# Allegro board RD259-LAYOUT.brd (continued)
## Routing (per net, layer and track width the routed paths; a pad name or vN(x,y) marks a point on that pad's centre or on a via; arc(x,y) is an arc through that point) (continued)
NETQ1_1: length 4.1
  TOP w0.3: RN14.1 64.12,11.82 Q1.1 ; RN14.1 64.06,14.08 RN13.2 ; RN14.1 64.14,14
NETR36_2: length 23.6
  BOTTOM w0.4: R36.2 19.93,34.37 20.81,34.37 21.08,34.09 ; R36.2 21.08,34.09 ; R36.2 19.92,33.84 21.34,33.84 ; 21.08,34.09 21.34,33.84 ; 21.34,33.84 21.94,33.84 26.89,28.88 26.89,22.69 27.97,21.61 ; 27.97,21.61 28.18,21.41 R37.1 27.97,20.41 27.97,21.61
NETR61_2: length 16.9
  TOP w1: 26.06,2.56 25.1,2.56 24.69,2.15 24.69,1.03 24.86,0.86 29.54,0.86 29.65,0.97 29.65,2.28 29.38,2.55 25.68,2.55 25.51,2.38 25.51,2.01 25.76,1.75 28.6,1.75
RES: length 104
  TOP w0.3: 73.19,27.21 73.19,27.63 73.07,27.75 ; 73.19,27.21 73.07,27.33 ; 73.19,27.21 74.01,26.39 74.79,26.39 ; 73.07,27.75 73.07,27.33 ; 73.07,27.75 72.87,27.95 ; 73.07,27.33 73.07,26.9 ; 73.83,26.15 74.03,25.94 74.83,25.94 ; 73.83,26.15 73.07,26.9 ; 73.83,26.15 v1(75.13,26.15) ; 68.14,25.63 68.14,25.1 68.15,25.1 ; 68.14,25.63 68.14,25.67 ; 68.14,25.63 68.38,25.4 68.38,25.15 R65.1 67.94,24.95 67.94,25.47 68.14,25.67 ; 72.87,27.95 72.87,27.11 73.07,26.9 ; 72.87,27.95 R38.2 ; 72.87,27.95 72.87,27.97 72.86,27.98 ; 70.81,29.92 70.99,29.75 C38.2 72.68,29.92 70.81,29.92 ; 70.81,29.92 70.19,30.55 IC4.4 69.23,30.54 68.42,30.54 68.14,30.26 68.14,25.67 ; R66.1 63.92,6.59
  TOP w1: 63.92,6.59 v1(65.26,6.59) ; C38.2 72.86,27.98
  BOTTOM w0.3: 65.64,6.96 65.64,6.37 65.45,6.18 65.12,6.18 64.97,6.33 64.97,6.34 64.97,6.83 ; 65.64,6.96 65.28,6.59 v1(65.26,6.59) ; 65.64,6.96 68.17,9.49 68.17,10.93 ; 32.15,19.98 30.2,19.98 R37.2 ; 32.15,19.98 31.94,20.2 ; 32.15,19.98 34.14,18 49.05,18 55.75,11.3 67.77,11.3 ; 31.78,20.35 31.63,20.51 30.29,20.51 30.13,20.35 ; 31.78,20.35 31.94,20.2 ; 31.78,20.35 30.13,20.35 ; 31.94,20.2 R37.2 ; 64.97,6.83 64.97,6.84 65.16,7.03 65.71,7.03 ; 64.97,6.83 64.94,6.8 ; 68.17,10.93 68.13,10.93 67.77,11.3 ; 68.17,10.93 68.17,11.3 ; 68.17,10.93 68.23,10.93 68.59,11.3 ; 30.13,20.35 R37.2 ; 75.39,26.12 75.39,25.73 75.1,25.44 ; 67.77,11.3 68.17,11.3 ; 75.1,25.44 75.1,15.5 70.9,11.3 68.59,11.3 ; 75.1,25.44 75.1,26.15 ; 68.17,11.3 68.59,11.3
SCK: length 2.1
  TOP w1: SCK.1 63.89,2.72 63.89,4.76 R66.2
SD: length 12.6
  TOP w0.4: 23.26,28.8 v1(23.06,29.01) ; 23.26,28.8 22.75,28.8 22.75,29.19 22.77,29.2 23.14,29.2 23.54,28.8 ; 23.26,28.8 23.54,28.8 ; 23.51,28.69 24.89,28.69 IC2.7 23.64,28.71 23.54,28.8
  BOTTOM w0.4: 23.66,29.07 24.2,29.07 24.45,28.82 ; 23.66,29.07 23.11,29.07 v1(23.06,29.01) ; 23.66,29.07 23.3,29.43 22.95,29.43 22.71,29.2 22.71,28.85 22.78,28.78 23.36,28.78 ; 23.36,28.78 23.14,29.01 v1(23.06,29.01) ; 23.36,28.78 23.59,28.56 24.8,28.56 R63.1 24.71,28.56 24.45,28.82 ; 23.36,28.78 24.42,28.78 24.45,28.82 ; 22.97,29.01 v1(23.06,29.01)
SDI: length 2.7
  TOP w1: 67.52,5.89 67.52,5.85 66.64,4.98 SDI.1
SDO: length 2
  TOP w1: R68.2 61.57,4.71 61.57,2.75 SDO.1
TX: length 36.1
  TOP w0.5: 21.17,59.22 v3(21.11,59.17)
  TOP w1: 21.11,61.74 CTX.2 ; CTX.2 21.17,65.51 ; CTX.2 21.17,59.36 ; 22.13,61.05 22.37,61.29 22.37,62.29 21.92,62.73 21.92,66 21.63,66.3 ; 22.13,61.05 22.08,61 22.08,60.27 21.19,59.38 ; 22.13,61.05 22.13,58.84 21.6,58.32 20.51,58.32 19.91,58.91 19.91,60.23 ; 21.19,59.29 21.19,59.38 ; 21.19,59.38 21.17,59.36 ; 21.17,59.36 21.11,59.3 v3(21.11,59.17) 20.98,59.17 20.45,59.7 ; 21.17,59.36 21.17,59.22 ; 20.45,59.7 19.91,60.23 ; 20.45,59.7 20.45,64.79 21.17,65.51 ; 19.91,60.23 19.91,65.4 20.14,65.62 ; 21.17,65.51 19.78,66.89 ; X.1 19.96,67.11
  vias: v5(20.08,67.05) v5(20.08,67.05)
U: length 78
  TOP w0.4: v1(12.62,38.91) 12.57,38.85 12.35,38.85 12.01,38.51 8.88,38.51
  TOP w0.5: 8.88,38.51 9.13,38.26 IC2.21 12.33,38.26 12.33,38.56 12.62,38.85 ; 9.35,38.91 v1(12.62,38.91) 12.62,38.85 12.62,38.85 ; 9.35,38.91 8.48,38.91 ; 9.35,38.91 8.17,40.08 8.15,40.08 ; 12.62,38.9 12.62,38.85 ; 12.62,38.85 12.62,38.29 12.58,38.25
  TOP w1: 9.51,44.06 9.05,43.6 ; 9.51,44.06 9.51,46.04 ; 9.51,44.06 9.53,44.06 10.23,44.76 ; 9.05,43.6 9.05,46.5 ; 9.05,43.6 8.74,43.29 ; 9.67,51.88 11.17,51.88 ; 10.23,44.76 10.93,45.46 ; 10.23,44.76 10.23,49.88 10.2,49.91 ; 10.93,45.46 10.93,50.05 11.1,50.22 ; 10.93,45.46 10.93,45 8.15,42.21 ; 8.15,39.24 7.83,39.55 7.83,42.38 8.15,42.69 ; 8.15,39.24 8.15,42.21 ; 8.15,39.24 8.88,38.51 ; 9.51,46.04 9.51,47.34 ; 9.51,46.04 9.05,46.5 ; 9.51,47.34 9.51,48.27 ; 9.51,47.34 7.55,49.31 7.55,49.86 7.93,49.86 9.51,48.27 ; 8.15,42.21 8.15,42.69 ; 8.15,42.69 8.74,43.29 ; 9.77,50.17 9.51,49.92 9.51,48.27 ; 9.05,46.5 8.74,46.81 ; 8.74,46.81 6.77,48.78 v1(6.77,49.14) ; 8.74,46.81 8.74,43.29
  BOTTOM w1: 7.85,51.22 7.85,52.06 7.2,52.71 5.87,52.71 5.44,52.28 5.44,49.43 v1(5.73,49.14) v1(6.77,49.14) 8.46,50.83 8.46,51.33 ; v1(12.62,38.91) 13.81,38.91 C15.1 13.94,39.04 13.86,39.13
  vias: v5(5.89,51.19) v5(5.89,51.19)
V: length 83
  TOP w0.4: 9.61,30.21 9.27,30.55 7.43,30.55 6.99,31 6.27,31 ; 9.61,30.21 9.95,29.88 ; 9.61,30.21 6.34,30.21 6.52,29.68 ; 11.19,29.88 IC2.26 11.23,29.86 11.28,29.81 11.28,29.8 11.4,29.68 11.51,29.57 12.18,29.57 12.35,29.41 ; 10.07,29.76 9.17,28.86 8.54,28.86 ; 9.95,29.88 9.11,29.88 ; 9.95,29.88 10.19,29.88 ; 2.63,30.11 2.17,30.56
  TOP w0.5: 11.19,29.88 10.19,29.88
  TOP w1: 4.17,28.01 2.22,28.01 1.17,29.06 ; 4.17,28.01 4.28,28.12 ; 4.17,28.01 8.01,28.01 8.86,28.86 ; 1.13,31.82 1.17,31.82 ; 1.13,31.82 1.13,29.1 1.17,29.06 ; 1.13,31.82 1.13,32.06 1.58,32.51 2.94,32.51 ; 1.17,31.82 1.17,29.06 ; 1.17,31.82 1.5,32.15 2.32,32.15 4.37,30.11 ; 4.37,30.11 4.37,31.07 2.94,32.51 ; 4.37,30.11 5.98,30.11 ; 4.37,30.11 3.12,28.86 ; 4.37,30.11 2.63,30.11 ; 5.98,30.11 6.52,29.68 ; 5.98,30.11 6.11,30.11 ; 5.98,30.11 3.58,32.51 2.94,32.51 ; 6.52,29.68 6.41,29.68 ; 6.52,29.68 5.72,29.6 4.22,29.6 v1(3.75,29.14) ; 6.52,29.68 9.11,29.68 ; 3.12,28.86 8.54,28.86 9.24,29.55 9.11,29.68 ; 3.12,28.86 1.37,28.86 ; 12.32,29.68 9.11,29.68
  BOTTOM w0.4: 13.68,29.27 13.25,29.7
  BOTTOM w1: 13.55,29.52 13.33,29.52 13.15,29.7 ; 13.55,29.52 13.37,29.7 13.15,29.7 ; 13.55,29.52 13.68,29.39 C14.1 ; 13.15,29.7 v1(12.38,29.7)
  BOTTOM w1.2: 3.18,28.56 3.18,31.96 ; 3.18,28.56 2.78,28.16 ; 3.18,28.56 3.18,28.16 2.78,28.16 ; 3.18,28.56 v1(3.75,29.14) 3.75,30.66 3.82,30.72 3.82,31.33 3.18,31.96 ; 3.18,31.96 2.61,32.53 1.77,32.53 1.77,32.52 1.05,31.79 1.05,31.42 1.05,31.42 1.05,29.36 1.13,29.27 1.13,29.26 2.22,28.17 ; 2.78,28.16 2.69,28.16
  vias: v6(2.17,30.56)
VM: length 38.5
  TOP w1: 33.89,2.64 33,1.75 32.03,1.75 ; 33.89,2.64 v4(34.63,3.38) 34.03,3.38 33.89,3.24 ; 33.89,2.64 33.89,3.24 ; 33.89,3.24 33.89,5.02 34.32,5.45 35.4,5.45 35.94,4.91 35.94,1.11 35.69,0.86 31.38,0.86 31.38,2.52 33.18,2.52 33.89,3.24 ; 33.89,3.24 33.6,2.94
  BOTTOM w1: 33.72,4.28 33.72,4.93 34.34,5.54 35.49,5.54 35.87,5.16 v1(35.87,1.02) 35.87,1.02 35.72,0.86 32.61,0.86 32.5,0.98 32.5,2.35 32.77,2.63 33.28,2.63 33.72,3.07 33.72,4.28 ; 33.72,4.28 v4(34.63,3.38)
  vias: v1(33.91,1.11) v1(34.93,1.06)
VM+310V: length 186.7
  TOP w0.4: v2(8.53,34.84) 8.77,34.84 9.06,34.55 ; 8.54,34.8 8.54,34.81 ; v2(8.54,33.63) 8.61,33.56
  TOP w0.5: 9.06,34.55 11.24,34.55 ; 8.61,33.56 11.17,33.56
  TOP w1: 8.98,34.9 8.92,34.96 7.94,34.96 7.79,34.81 7.79,34.08 ; 8.98,34.9 9.09,34.79 ; 8.98,34.9 7.87,34.9 ; 9.09,34.79 8.58,34.79 8.54,34.83 ; 9.09,34.79 9.33,34.55 ; 9.79,34.09 11.75,34.09 ; 9.79,34.09 9.33,34.55 ; 9.79,34.09 9.26,33.56 9.2,33.49 8.37,33.49 7.79,34.08 ; 22.48,0.86 22.5,0.88 22.6,0.88 22.6,3.9 ; 9.33,34.55 8.87,34.08 8.54,34.08 ; 8.54,34.08 8.54,33.63 v2(8.54,33.63) ; 8.54,34.08 7.79,34.08 ; 8.54,34.08 8.54,34.83 ; 8.54,34.83 v2(8.53,34.84)
  TOP w1.2: 22.22,0.96 21.8,1.37
  TOP w2: 19.16,2.96 17.03,5.1 ; 19.16,2.96 20.1,3.9 22.6,3.9 ; 19.16,2.96 20.75,1.37 21.8,1.37 ; 17.03,5.1 15.48,5.1 15.48,6.64 ; 17.03,5.1 15.48,6.64 ; 17.03,5.1 17.05,5.1 v1(17.22,5.27) 17.39,5.44 ; 22.6,3.9 21.17,2.47 v2(19.71,2.47) ; 22.6,3.9 C61.1 18.25,4.58 17.39,5.44 ; 17.39,5.44 15.48,7.35 ; 15.48,7.35 C63.1 ; 15.48,7.35 15.48,6.64
  BOTTOM w0.4: R36.1 17.85,34.1 17.55,34.4 17.21,34.4 16.91,34.09 ; R36.1 17.02,34.09 ; R36.1 17.6,33.85 17.27,33.85 17.02,34.09 ; 16.91,34.09 10.17,34.09 ; 16.91,34.09 17.02,34.09 ; 8.67,34.7 8.7,34.67 9.31,34.67 9.89,34.09 ; 8.67,34.7 9.57,34.7 10.17,34.09 ; 8.67,34.7 v2(8.53,34.84) ; 8.91,33.8 8.68,33.8 8.53,33.64 ; 8.91,33.8 9.59,33.8 9.89,34.09 ; 8.91,33.8 9.21,34.09 9.89,34.09 ; 8.91,33.8 8.74,33.63 v2(8.54,33.63) ; 9.89,34.09 10.17,34.09 ; 10.17,34.09 8.82,32.75 8.54,32.75
  BOTTOM w1: 19.76,2.11 18.85,3.02 18.85,5.03
  BOTTOM w1.2: 21.26,6.5 15.79,6.5 15.79,4.83 16.22,4.4 17.19,4.4 ; 21.26,6.5 23.04,6.5 23.04,5.62 ; 21.26,6.5 8.97,18.79 ; 16.48,5.49 16.61,5.62 23.04,5.62 ; 23.04,5.62 23.04,4.41 ; 17.19,4.4 17.19,4.41 23.04,4.41 ; 17.19,4.4 20.63,0.96 22.79,0.96 23.04,1.21 23.04,3.2 ; 18.85,3.6 19.25,3.2 23.04,3.2 ; 23.04,4.41 23.04,3.2
  BOTTOM w2: 8.54,32.75 7.59,33.71 7.59,34.84 8.52,34.84 v2(8.53,34.84) 8.53,33.64 v2(8.54,33.63) 8.54,32.75 ; 8.54,32.75 8.54,19.22 ; 15.41,11.15 8.97,17.59 ; 15.41,11.15 16.61,9.94 16.61,5.62 17.49,6.5 18.27,7.28 19.2,7.28 17.34,9.14 ; 15.41,11.15 15.41,5.73 16.38,4.75 ; 8.97,17.59 8.54,18.01 8.54,19.22 ; 8.97,17.59 8.97,18.79 8.54,19.22
  vias: v1(18.3,5.03)
VREG: length 148.7
  TOP w0.3: 71.16,32.5 71.35,32.5 ; 71.57,32.91 71.89,32.63
  TOP w0.35: IC4.7 71.16,32.5 ; 71.92,32.19 71.87,32.14 71.58,32.14 71.21,32.5
  TOP w0.5: 73.32,32.19 71.92,32.19 71.48,32.63 72.02,32.63 72.5,33.11 ; 73.32,32.19 74.44,32.19 74.73,32.49 74.73,32.98 74.6,33.11 72.75,33.11 ; 73.32,32.19 73.78,32.65 ; v1(73.12,22.68) 73.13,22.67 ; 69.77,18.96 69.44,19.29 ; 69.77,18.96 69.77,18.58 v1(69.81,18.54) ; 69.77,18.96 70.17,18.56 ; 69.44,19.29 69.44,18.41 69.58,18.27 69.58,18.21 69.87,18.21 70.17,18.51 70.17,18.56 ; 69.44,19.29 68.34,20.39 R24.2 ; 73.78,32.65 v1(73.93,32.65) 73.94,32.67 v1(74.61,32.67) 74.47,32.81 ; 73.78,32.65 73.85,32.73 ; 73.78,32.65 73.04,32.65 72.84,32.86 72.84,33.03 72.75,33.11 ; 76.27,41.85 76.54,41.58 76.54,41.19 76.22,40.87 76,40.87 76,42.12 ; 76.27,41.85 76,42.12 ; 76.27,41.85 76.27,41.21 v1(76.31,41.17) ; 70.17,18.56 70.17,18.69 ; 75.67,42.45 R3.1 74.22,42.48 R31.1 R15.2 59.99,42.48 JP3.1 60.2,42.77 75.35,42.77 75.67,42.45 ; 75.67,42.45 76,42.12 ; 71.16,32.5 71.77,33.11 72.5,33.11 ; 72.5,33.11 72.75,33.11 ; 74.47,32.8 74.47,32.81 ; 74.47,32.81 74.53,32.86 74.53,32.97 74.61,33.06 ; 76.38,22.67 v1(76.39,22.66)
  TOP w1: 73.13,22.67 76.38,22.67
  BOTTOM w0.3: 71.6,30.67 71.86,30.93 71.86,31.91 C27.1
  BOTTOM w0.5: 75.89,32.93 76.44,33.47 ; 75.89,32.93 74.93,32.93 74.67,32.67 v1(74.61,32.67) 74.61,32.66 73.93,32.66 v1(73.93,32.65) ; 75.89,32.93 76.18,32.93 ; 76.44,33.47 76.44,40.59 ; 76.44,33.47 76.44,31.47 ; 73.08,22.78 73.12,22.74 v1(73.12,22.68) ; 73.08,22.78 72.66,23.2 ; 73.08,22.78 73.08,23.5 ; 73.08,22.78 73.08,22.72 v1(73.12,22.68) ; 70.65,18.79 73.1,21.23 73.1,21.82 ; 70.65,18.79 69.97,18.11 67.92,18.11 R2A.2 67.81,18.54 ; 70.65,18.79 70.61,18.82 70.1,18.82 ; 72.87,23.72 72.8,23.65 72.21,23.65 ; 72.87,23.72 73.08,23.5 ; 72.87,23.72 72.65,23.94 72.65,25.17 R1.1 ; 70.1,18.82 v1(69.81,18.54) 69.77,18.5 67.85,18.5 67.81,18.54 ; 70.1,18.82 72.66,21.39 ; 70.1,18.82 69.37,18.82 69.25,18.71 67.98,18.71 67.81,18.54 ; 72.66,23.2 72.77,23.2 73.08,23.5 ; 72.66,23.2 72.66,21.39 ; 72.66,23.2 72.21,23.65 ; 75.97,31.94 76.09,31.94 76.15,31.88 76.15,31.76 76.44,31.47 ; 72.66,21.39 73.1,21.82 ; 73.1,21.82 73.1,22.66 v1(73.12,22.68) ; 72.26,32.89 72.32,32.95 75.56,32.95 ; 76.44,31.47 76.44,28.04 76.39,27.99 ; 71.73,32.34 72.01,32.61 73.89,32.61 v1(73.93,32.65) ; 76.39,27.99 76.39,23.33 ; 76.39,27.99 76.68,27.71 ; 76.39,23.33 76.68,23.04 ; 76.39,23.33 76.04,22.98 76.04,22.69 76.34,22.39 76.64,22.39 76.64,22.42 76.77,22.54 76.77,22.95 76.68,23.04 ; 76.39,23.33 v1(76.39,22.66) ; 76.68,23.04 76.68,27.71 ; v1(73.93,32.65) 73.9,32.65 ; 67.81,18.54 67.69,18.67 ; 76.44,40.59 76.44,40.99 76.31,41.12 v1(76.31,41.17) ; 76.44,40.59 76.04,40.98 76.04,41.47 76.38,41.47 76.68,41.18 76.68,27.71 ; 72.21,23.65 72.21,25.39
VSP: length 13.1
  TOP w1: 49.46,4.45 49.46,8.35 D2.1
  TOP w1.2: v4(48.83,3.38) 48.83,8.6 D2.1 50.49,10.26 R6.1
VSP1: length 38.8
  TOP w0.3: 69.46,11.37 69.46,11.11 ; 69.46,11.37 69.27,11.37 69.24,11.33 69.22,11.35 69.22,11.69 69.46,11.93 ; 69.46,11.37 69.46,11.93 ; 69.46,11.37 69.67,11.37 ; 69.46,11.11 69.46,10.98 ; 69.46,11.11 69.55,11.11 69.55,11.25 ; 69.46,11.11 69.02,11.11 69.16,11.25 69.27,11.25 ; 69.55,11.25 69.67,11.37 ; 69.55,11.25 69.69,11.25 ; 69.67,11.37 69.73,11.42 69.73,12.19 ; 69.67,11.37 69.68,11.37 ; 67.94,8.86 69.06,9.98 ; 67.94,8.86 67.94,8.02 67.72,7.8 ; 67.94,8.86 67.72,8.63 ; 69.06,9.98 69.06,10.62 69.25,10.81 69.27,10.81 ; 69.06,9.98 69.27,10.19 ; C9.1 71.09,26.31 71.09,28.76 70.91,28.94 ; C9.1 70.91,26.26 70.91,28.94 ; C9.1 70.88,26.2 69.87,25.19 ; 67.72,7.8 R67.1 67.52,7.79 ; 67.72,7.8 67.72,8.63 ; 69.46,11.93 69.73,12.19 ; 70.35,26.28 70.35,26.01 69.87,25.54 69.87,25.19 ; 69.87,25.19 69.87,25.18 69.87,21.53 71.58,19.81 71.58,14.04 69.73,12.19 ; 69.27,10.81 69.27,10.96 R12.2 69.46,10.98 ; 69.27,10.81 69.27,10.19 ; 69.15,29.92 69.19,29.89 69.96,29.89 70.91,28.94 ; 69.46,10.98 69.46,10.38 69.27,10.19 ; 67.52,7.79 67.32,7.99 67.32,8.24 67.52,8.44 ; 67.52,7.79 67.52,8.44 ; 67.52,8.44 67.72,8.63
W: length 112.7
  TOP w0.203: 8,10.08 7.94,10.08 7.53,10.5 7.53,12.03 8.16,12.66 9.13,12.66 9.26,12.53 9.85,11.94 9.98,11.81 10.04,11.81 11.12,12.9 11.12,17.37
  TOP w0.4: 12.01,22.44 12.8,21.64 v1(12.87,21.64) ; 9.36,18.01 8.97,18.4
  TOP w1: 9.26,11.34 9.85,11.94 9.97,12.05 9.97,15.78 10.62,16.43 ; 9.26,11.34 9.26,10.5 8.84,10.92 ; 9.26,11.34 8.84,10.92 ; 9.26,11.34 9.26,15.51 ; 9.26,11.34 9.51,11.09 10.62,11.09 ; 8.25,14.5 9.26,15.51 ; 8.25,14.5 8.25,13.54 ; 8.25,14.5 8.25,16.54 ; 9.26,15.51 10.62,16.87 ; 9.26,15.51 9.26,16.97 9.53,17.24 ; 8.28,18.01 8.25,18.04 8.25,17.08 ; 8.28,18.01 9.53,18.01 ; 8.28,18.01 8.47,18.21 8.47,20.25 ; 8.25,16.54 8.25,17.08 ; 8.25,16.54 7.45,15.74 7.45,11.26 7.53,11.17 8.43,10.28 8.43,10.02 ; 8.25,17.08 7.51,17.83 7.51,18.11 7.71,18.31 7.71,19.5 8.47,20.25 ; v1(12.87,21.64) 12.44,22.08 11.08,22.08 ; 8.84,10.92 8.25,11.5 8.25,13.54 ; 8.84,10.92 8.84,12.96 8.25,13.54 ; 10.62,16.43 10.62,11.09 ; 10.62,16.43 10.62,16.87 ; 11.08,22.08 11.08,21.98 9.53,20.42 ; 11.08,22.08 10.29,22.08 9.53,21.31 ; 8.47,20.25 8.97,20.76 ; 10.62,11.09 10.62,8.95 9.9,8.95 9.9,9.28 8.58,9.28 8.43,9.43 8.43,10.02 ; 8.43,10.02 7.74,10.71 ; 10.62,16.87 10.62,18.01 ; 9.53,21.31 9.53,20.42 ; 9.53,21.31 8.97,20.76 ; 9.53,20.42 9.53,19.1 ; 9.53,19.1 10.62,18.01 ; 9.53,19.1 9.53,18.01 ; 10.3,18.01 9.53,17.24 ; 10.3,18.01 9.53,18.01 ; 10.3,18.01 10.62,18.01 ; 9.53,17.24 9.53,18.01 ; 8.97,20.76 8.97,18.4
  BOTTOM w0.4: 13.56,20.92 C13.1 14.58,20.98 ; 13.56,20.92 12.93,20.92 12.71,21.14 ; 13.56,20.92 13.34,21.14 ; 14.36,21.2 14.3,21.14 13.34,21.14 ; 14.36,21.2 14.58,20.98 ; 14.36,21.2 14.14,21.41 13.92,21.41 ; 12.49,21.56 12.92,21.56 ; 12.49,21.56 12.49,21.35 12.71,21.14 ; 12.49,21.56 12.49,21.77 12.73,22.01 13.1,22.01 13.54,21.56 ; 12.92,21.56 13.54,21.56 ; 12.92,21.56 12.87,21.61 v1(12.87,21.64) ; 12.92,21.56 13.34,21.14 ; 13.92,21.41 13.69,21.41 13.54,21.56 ; 13.92,21.41 13.77,21.56 ; 14.58,20.98 14.58,21.13 14.14,21.56 13.77,21.56 ; 13.77,21.56 13.54,21.56 ; 13.34,21.14 13.54,21.34 13.54,21.56 ; 13.34,21.14 12.71,21.14
  BOTTOM w1: 9.85,9.19 9.85,9 10.09,8.77 10.09,9.19 9.85,9.19 ; 9.85,9.19 9.26,9.19 7.84,10.61 7.84,11.79 9.59,11.79 v1(9.85,11.53) ; 9.85,9.19 v1(9.85,11.53) ; v1(9.85,11.53) 9.47,11.15 9.47,11.07 8.3,11.07 8.24,11.01 ; v1(9.85,11.53) 10.35,11.04 10.35,9
  vias: v5(8.82,10.92)

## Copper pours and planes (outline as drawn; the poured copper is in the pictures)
U on TOP: 4.28,48.21 3.87,48.61 3.87,50.45 3.94,50.93 3.95,50.93 4.12,51.36 4.37,51.8 4.63,52.26 4.87,52.66 5.16,53.04 5.54,53.32 5.97,53.58 7.08,54.22 10.96,54.22 12.02,53.15 12.02,49.77 11.43,49.25 7.94,49.25 6.91,48.21

Small or netless copper shapes (teardrops, artwork), in the pictures only: 16 on TOP, 31 on BOTTOM

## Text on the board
Ref Des/Silkscreen Top: 3-Phase BL Motor Driver | RD259
